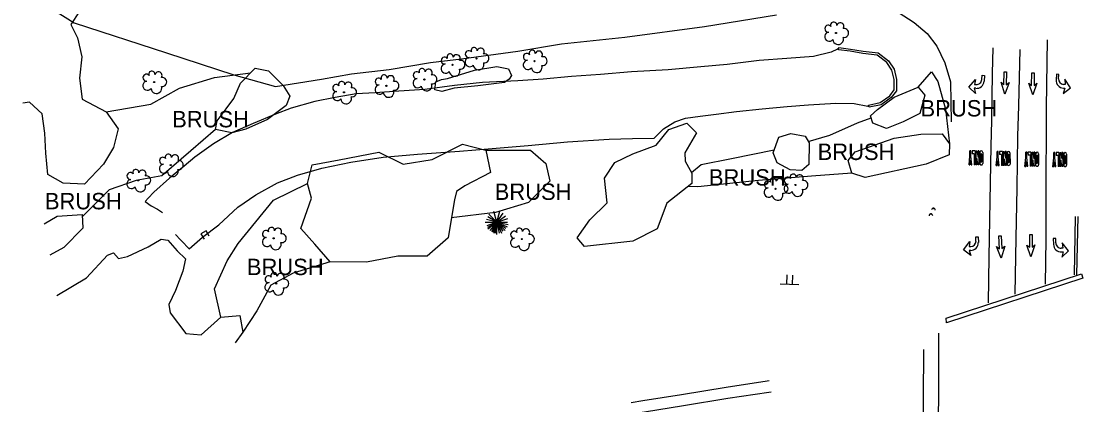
# Model space of a CAD drawing. Extents: x 2129547 to 2134906, y 657330 to 659734.
# Drawn here: x 2132031.2 to 2132484.8, y 657638.7 to 657802.6 of the extents above; entities that cross this region are included whole.
import ezdxf

# ---------------------------------------------------------------- set-up
doc = ezdxf.new("R2010")
doc.units = 0
for name, color, linetype in [('Default', 7, 'Continuous'), ('DR_X_Culvert', 7, 'Continuous'), ('DR_X_Drainage_Area', 7, 'Continuous'), ('PM_X_Arrows', 7, 'Continuous'), ('PM_X_Cells', 7, 'Continuous'), ('PM_X_Channelizing_Line', 7, 'Continuous'), ('PM_X_CL_Double_Solid', 7, 'Continuous'), ('PM_X_Crosswalk', 7, 'Continuous'), ('PM_X_Lane_Line', 7, 'Continuous'), ('PM_X_Stop_Line', 7, 'Continuous'), ('PV_X_Walk', 7, 'Continuous'), ('RD_X_Fence', 7, 'Continuous'), ('SN_X_Public', 7, 'Continuous'), ('UT_X_Misc_Cells', 7, 'Continuous'), ('VG_X_Cells', 7, 'Continuous'), ('VG_X_Shrub_Line_Lt', 7, 'Continuous'), ('VG_X_Text', 7, 'Continuous'), ('VG_X_Tree_Line_Lt', 7, 'Continuous')]:
    doc.layers.add(name, color=color, linetype=linetype)

# ---------------------------------------------------------------- blocks, each defined once
blk = doc.blocks.new('PIPE')
at = {"layer": 'Default'}
for p, q in [((0.135, 0.067), (0, 0.067)), ((0, 0.067), (0, -0.067)), ((0, -0.067), (0.135, -0.067))]:
    blk.add_line(p, q, dxfattribs=at)
blk = doc.blocks.new('DM')
at = {"layer": 'UT_X_Misc_Cells'}
blk.add_circle((0, 0), 0.00254, dxfattribs=at)
blk.add_arc((0.01016, 0), 0.01016, 90, 270, dxfattribs=at)
blk = doc.blocks.new('POINT_DISPLAY')
at = {"layer": 'Default'}
blk.add_line((0, 0), (0, 0), dxfattribs=at)
blk = doc.blocks.new('SGN2P')
at = {"layer": 'Default'}
for p, q in [((0, 0.0061), (-0.0203, 0.0061)), ((0, 0.0203), (0, -0.0203)), ((0, -0.0061), (-0.0203, -0.0061))]:
    blk.add_line(p, q, dxfattribs=at)
blk.add_blockref('POINT_DISPLAY', (0, 0), dxfattribs=at)
blk = doc.blocks.new('TREE')
at = {"layer": 'VG_X_Cells'}
blk.add_circle((0, 0), 0.00305, dxfattribs=at)
for centre, radius, start, end in [((-0.0125, 0.0428), 0.0167, 354.0047, 205.97412), ((-0.0362, -0.0197), 0.0251, 96.17219, 320.57371), ((-0.042, 0.0237), 0.0187, 39.06254, 279.54124), ((0.0232, 0.0359), 0.0197, 323.82996, 165.0376), ((0.0439, 0.0005), 0.0243, 259.14531, 101.45961), ((0.012, -0.0331), 0.029, 184.94757, 19.45715)]:
    blk.add_arc(centre, radius, start, end, dxfattribs=at)
blk = doc.blocks.new('ETREE')
at = {"layer": 'VG_X_Cells'}
for p, q in [((0, 0), (-0.0157, 0.0586)), ((0, 0), (0.016, 0.0597)), ((-0.0627, 0), (0, 0)), ((0, 0), (-0.056, 0.015)), ((0, 0), (-0.0545, -0.0198)), ((0, 0), (-0.0506, -0.029)), ((0, 0), (-0.0496, 0.0292)), ((0, 0), (-0.0496, -0.038)), ((0, 0), (-0.0443, 0.0443)), ((0, 0), (-0.0374, -0.044)), ((0, 0), (-0.0294, -0.051)), ((0, 0), (-0.0211, -0.0551)), ((0, 0), (-0.016, -0.0617)), ((0, 0), (-0.0069, -0.0583)), ((0, 0), (0.0337, 0.0493)), ((0, 0), (0.0464, 0.0356)), ((0, 0), (0.0602, 0.0204)), ((0, 0), (0.0573, 0.0012)), ((0, -0.0665), (0, 0)), ((0, 0), (0.0117, -0.0589)), ((0, 0), (0.0246, -0.0593)), ((0, 0), (0.0322, -0.0482)), ((0, 0), (0.0456, -0.0447)), ((0, 0), (0.0485, -0.0324)), ((0, 0), (0.0567, -0.0247)), ((0, 0), (0.0613, -0.0122))]:
    blk.add_line(p, q, dxfattribs=at)
blk = doc.blocks.new('PMLFT')
at = {"layer": 'PM_X_Cells'}
for points in [[(-0.57, 0), (-0.57, 0), (-0.57, 0.17), (0, 0), (-0.65, 0.76), (-1.54, 0.08), (-0.98, 0.17), (-0.98, -0.01)], [(-1.56, -0.59), (-2.03, -0.59), (-2.03, -0.85), (-1.4, -0.85)]]:
    blk.add_lwpolyline(points, dxfattribs=at)
for centre, radius, end in [((-1.56, -0.01), 0.583, 0), ((-1.4, -0.01), 0.833, 0.9085)]:
    blk.add_arc(centre, radius, 270, end, dxfattribs=at)
blk = doc.blocks.new('PMRT')
at = {"layer": 'PM_X_Cells'}
for points in [[(-1.56, 0.59), (-2.03, 0.59), (-2.03, 0.85), (-1.4, 0.85)], [(-0.57, 0), (-0.57, 0), (-0.57, -0.17), (0, 0), (-0.65, -0.76), (-1.54, -0.08), (-0.98, -0.17), (-0.98, 0.01)]]:
    blk.add_lwpolyline(points, dxfattribs=at)
for centre, radius, start in [((-1.56, 0.01), 0.583, 360), ((-1.4, 0.01), 0.833, 359.0915)]:
    blk.add_arc(centre, radius, start, 90, dxfattribs=at)
blk = doc.blocks.new('PMTHR')
at = {"layer": 'PM_X_Cells'}
blk.add_lwpolyline([(0, 0), (-1.27, -0.44), (-1.02, -0.13), (-2.41, -0.13), (-2.41, 0.13), (-1.02, 0.13), (-1.27, 0.44)], close=True, dxfattribs=at)
blk = doc.blocks.new('PMON8')
at = {"layer": 'Default'}
for p, q in [((-2.03, 0.44), (0, 0.44)), ((-2.03, 0.44), (-2.03, 0.32)), ((-2.03, 0.32), (-1.08, 0.32)), ((-2.03, 0.15), (-1.08, 0.32)), ((-2.03, 0.02), (-2.03, 0.15)), ((-2.03, 0.02), (0, 0.02)), ((-1.82, 0.99), (-0.21, 0.99)), ((-1.82, 0.57), (-0.21, 0.57)), ((-1.52, 0.87), (-0.51, 0.87)), ((-1.52, 0.7), (-0.51, 0.7)), ((0, 0.32), (-0.95, 0.15)), ((-0.95, 0.15), (0, 0.15)), ((0, 0.44), (0, 0.32)), ((0, 0.15), (0, 0.02)), ((-2.03, -0.11), (0, -0.11)), ((-2.03, -0.11), (-2.03, -0.53)), ((-2.03, -0.53), (-1.61, -0.53)), ((-1.27, -0.72), (-2.03, -0.72)), ((-2.03, -0.72), (-2.03, -0.85)), ((-1.27, -0.85), (-2.03, -0.85)), ((-1.61, -0.23), (-1.61, -0.53)), ((-1.61, -0.23), (0, -0.23)), ((0, -0.57), (-1.27, -0.72)), ((0, -0.99), (-1.27, -0.85)), ((0, -0.7), (-0.68, -0.78)), ((0, -0.87), (-0.68, -0.78)), ((0, -0.11), (0, -0.23)), ((0, -0.7), (0, -0.57)), ((0, -0.99), (0, -0.87))]:
    blk.add_line(p, q, dxfattribs=at)
for centre, radius, start, end in [((-1.82, 0.78), 0.212, 90, 270), ((-1.52, 0.78), 0.0847, 90, 270), ((-0.51, 0.78), 0.0847, 270, 90), ((-0.21, 0.78), 0.212, 270, 90)]:
    blk.add_arc(centre, radius, start, end, dxfattribs=at)
for p in [(-2.03, 0), (0, 0)]:
    blk.add_blockref('POINT_DISPLAY', p, dxfattribs=at)

msp = doc.modelspace()

# ---------------------------------------------------------------- linework, layer by layer
at = {"layer": 'DR_X_Culvert'}
msp.add_lwpolyline([(2132380.18, 657791.34), (2132385.27, 657790.69), (2132390.58, 657789.74), (2132397.07, 657789.05), (2132401.44, 657785.59), (2132403.82, 657782.03), (2132404.8, 657777.72), (2132404.86, 657772.86), (2132402.65, 657769.92), (2132398.29, 657766.85), (2132393.17, 657765.77), (2132392.96, 657766.75), (2132397.88, 657767.78), (2132401.94, 657770.65), (2132403.85, 657773.19), (2132403.8, 657777.6), (2132402.88, 657781.63), (2132400.69, 657784.9), (2132396.67, 657788.08), (2132390.43, 657788.75), (2132385.12, 657789.7), (2132380.05, 657790.34)], close=True, dxfattribs=at)
at = {"layer": 'DR_X_Drainage_Area'}
for points in [[(2132380.12, 657790.85), (2132379.71, 657790.64), (2132377.02, 657789.28), (2132369.47, 657787.52), (2132357.97, 657786.7), (2132346.22, 657785.71), (2132332.63, 657784), (2132321.33, 657783.02), (2132307.38, 657781.84), (2132291.69, 657780.87), (2132278.52, 657779.74), (2132266.09, 657778.87), (2132253.98, 657777.82), (2132243.17, 657777.07), (2132228.15, 657776.36), (2132216.1, 657775.1), (2132203.53, 657773.42), (2132192.43, 657772.68), (2132182.36, 657771.93), (2132174.14, 657771.53), (2132165.29, 657770.01), (2132156.52, 657768.21), (2132146.39, 657765.42), (2132139.8, 657762.88), (2132130.18, 657758.81), (2132121.36, 657754.96), (2132113.34, 657750.12), (2132105.36, 657744.47), (2132100.77, 657740.61), (2132094.51, 657735.45), (2132087.79, 657729.46), (2132085.4, 657726.95), (2132084.15, 657725.58), (2132086.69, 657723.69), (2132089.32, 657722.32), (2132091.49, 657720.85)], [(2132097.12, 657711.43), (2132099.19, 657709.17), (2132099.59, 657708.74), (2132102.91, 657705.35), (2132108.55, 657710.29), (2132115.54, 657715.63), (2132123.69, 657723.11), (2132131.42, 657728.43), (2132140.57, 657733.54), (2132149.16, 657736.74), (2132159.6, 657739.81), (2132171.88, 657742.33), (2132185.78, 657744.54), (2132200.38, 657745.79), (2132218.29, 657747.08), (2132232.31, 657748.22), (2132247.61, 657749.52), (2132264.45, 657750.98), (2132282.18, 657752.1), (2132292.14, 657752.43), (2132301.43, 657752.64), (2132305.35, 657756.55), (2132310.29, 657759.52), (2132314.83, 657761.14), (2132321.06, 657761.94), (2132327.88, 657762.81), (2132336.49, 657763.93), (2132347.51, 657765.07), (2132358.23, 657766.08), (2132367.29, 657766.77), (2132378.99, 657767.55), (2132386.84, 657767.34), (2132392.62, 657766.33), (2132393.07, 657766.25)]]:
    msp.add_lwpolyline(points, dxfattribs=at)
at = {"layer": 'PM_X_Channelizing_Line'}
for points in [[(2132468.44, 657690.19), (2132468.69, 657709.47), (2132468.69, 657733.18), (2132468.85, 657757.97), (2132468.93, 657765.72), (2132469.31, 657794.62)], [(2132445.93, 657791.25), (2132445.7, 657780.27), (2132445.35, 657760.17), (2132445.12, 657749.22), (2132444.69, 657725.73), (2132444.3, 657701.93), (2132444.04, 657682.21)]]:
    msp.add_lwpolyline(points, dxfattribs=at)
at = {"layer": 'PM_X_CL_Double_Solid'}
for p, q in [((2132480.86, 657694.16), (2132481.34, 657719.16)), ((2132481.86, 657694.14), (2132482.34, 657719.14))]:
    msp.add_line(p, q, dxfattribs=at)
at = {"layer": 'PM_X_Crosswalk'}
for points in [[(2132534.65, 657677.35), (2132530.77, 657661.09), (2132525.71, 657640.72), (2132521.24, 657623.89), (2132516.54, 657605.77), (2132512.45, 657589.14), (2132495.31, 657586.38), (2132478.53, 657583.9), (2132458.76, 657580.95), (2132439.37, 657577.96), (2132422.84, 657575.72), (2132422.84, 657591.79), (2132422.63, 657608.08), (2132422.81, 657625.36), (2132422.95, 657650.57), (2132422.99, 657669.31)], [(2132416.36, 657662.33), (2132416.31, 657641.39), (2132416.34, 657624.06), (2132416.32, 657608.43), (2132416.1, 657589.48), (2132416.03, 657573.91)]]:
    msp.add_lwpolyline(points, dxfattribs=at)
at = {"layer": 'PM_X_Lane_Line'}
msp.add_lwpolyline([(2132457.54, 657790.46), (2132456.92, 657766.41), (2132456.46, 657753.4), (2132456.28, 657731.21), (2132455.86, 657709.97), (2132455.41, 657685.95)], dxfattribs=at)
at = {"layer": 'PM_X_Stop_Line'}
msp.add_lwpolyline([(2132484.42, 657692.74), (2132426.26, 657673.7), (2132426, 657675.73), (2132483.79, 657694.67)], close=True, dxfattribs=at)
at = {"layer": 'PV_X_Walk'}
for points in [[(2132350.47, 657648.87), (2132349.63, 657648.74), (2132332.16, 657646.04), (2132313.12, 657642.92), (2132296.58, 657640.33), (2132291.56, 657639.54)], [(2132351.29, 657644.14), (2132350.37, 657644), (2132332.92, 657641.3), (2132313.88, 657638.18), (2132297.33, 657635.58), (2132292.42, 657634.81)]]:
    msp.add_lwpolyline(points, dxfattribs=at)
at = {"layer": 'RD_X_Fence'}
for points in [[(2132031.21, 657816.21), (2132053.76, 657801.86), (2132093.2, 657789.04), (2132121.96, 657779.72), (2132139.74, 657774.63), (2132159.35, 657777.78), (2132172.17, 657780.04), (2132188.33, 657781.96), (2132205.93, 657784.87), (2132219.21, 657786.45), (2132243.16, 657789.79), (2132261.84, 657792.9), (2132288.84, 657795.78), (2132322.87, 657800.28), (2132353.63, 657805.31)], [(2132405.58, 657806.42), (2132412.34, 657802.05), (2132417.89, 657797.32), (2132422.01, 657791.93), (2132425.42, 657784.82), (2132427.92, 657776.62), (2132428.17, 657759.63)]]:
    msp.add_lwpolyline(points, dxfattribs=at)
at = {"layer": 'VG_X_Shrub_Line_Lt'}
for points in [[(2132067.4, 657763.86), (2132086.53, 657767.12), (2132098.81, 657773.91), (2132113.7, 657778.52), (2132129.09, 657780.5)], [(2132414.07, 657774.36), (2132419.82, 657780.98), (2132422.46, 657776.82), (2132425.75, 657764.93), (2132427.52, 657750.2)], [(2132367.18, 657751.19), (2132376.38, 657753.94), (2132388.17, 657759.11), (2132393.99, 657761.34)], [(2132114.18, 657756.32), (2132103.64, 657747.13), (2132091.16, 657736.43), (2132080.27, 657734.55), (2132068.73, 657730.56), (2132057.25, 657719.05)], [(2132229.61, 657747.46), (2132248.67, 657747.43), (2132255.1, 657741.81), (2132256.8, 657734.28), (2132247.76, 657725.04), (2132233.65, 657720.86), (2132214.81, 657718.54)], [(2132317.32, 657737.98), (2132321.45, 657741.41), (2132334.37, 657743.96), (2132352.69, 657747.61)], [(2132385.74, 657737.61), (2132368.59, 657736.33), (2132345.9, 657734.51), (2132320.01, 657731.86), (2132315.84, 657731.96)], [(2132116.4, 657676.13), (2132113.67, 657688.18), (2132119.15, 657700.19), (2132123.77, 657707.53), (2132138.95, 657726.05), (2132153.43, 657733.29)], [(2132163.13, 657699.81), (2132147.24, 657694.91), (2132137.7, 657689.84), (2132131.82, 657678.8), (2132125.83, 657669.64)]]:
    msp.add_lwpolyline(points, dxfattribs=at)
at = {"layer": 'VG_X_Tree_Line_Lt'}
for points in [[(2132056, 657806.61), (2132052.44, 657801.19), (2132055.16, 657795.46), (2132057.13, 657787.3), (2132056.07, 657778.23), (2132057.18, 657769.26), (2132067.4, 657763.86), (2132072.65, 657756.58), (2132070.58, 657748.65), (2132066.39, 657741.45), (2132058.26, 657732.91), (2132049.04, 657733.34), (2132042.49, 657737.12), (2132041.64, 657746.25), (2132041.26, 657754.75), (2132040.17, 657762.95), (2132034.69, 657767.95), (2132031.9, 657767.58)], [(2132041.02, 657716), (2132046.53, 657719.23), (2132057.19, 657720.02), (2132057.57, 657714.09), (2132049.35, 657705.91), (2132043.39, 657702.61)], [(2132046.45, 657685.33), (2132059.1, 657692.85), (2132068.06, 657702.62), (2132070.65, 657703.56), (2132072.76, 657701.14), (2132076.51, 657702.05), (2132085.44, 657706.19), (2132090.88, 657709.46), (2132093.8, 657708.96), (2132097.75, 657704.41), (2132101.32, 657701.07), (2132100.24, 657695.78), (2132097.04, 657687.49), (2132094.23, 657681.54), (2132094.82, 657677.92), (2132101.48, 657669.2), (2132108.01, 657668.51), (2132116.4, 657676.13), (2132124.47, 657676.84), (2132125.83, 657669.64), (2132122.54, 657665.21)]]:
    msp.add_lwpolyline(points, dxfattribs=at)
for points in [[(2132121.9, 657769.55), (2132124.83, 657776.12), (2132131.11, 657782.57), (2132136.83, 657781.43), (2132143.03, 657775.15), (2132145.93, 657770.55), (2132144.33, 657766.6), (2132136.32, 657760.5), (2132127.03, 657756.47), (2132121.15, 657754.91), (2132114.18, 657756.32), (2132114.82, 657760.05), (2132118.71, 657765.12)], [(2132213.22, 657778.13), (2132224.69, 657781.64), (2132234.25, 657783.23), (2132239.23, 657782.25), (2132240.52, 657779.41), (2132239.46, 657777.78), (2132237.49, 657776.44), (2132226.1, 657774.94), (2132216.09, 657774.01), (2132210.71, 657772.57), (2132207.79, 657773.25), (2132208.19, 657776.6), (2132210.6, 657777.68)], [(2132396.77, 657764.9), (2132403.82, 657770.08), (2132414.07, 657774.36), (2132416.98, 657770.91), (2132414.8, 657763.1), (2132407.68, 657759.53), (2132400.59, 657756.75), (2132394.81, 657758.95), (2132393.73, 657762.07)], [(2132317.46, 657733.24), (2132306.76, 657724.81), (2132302.73, 657713.92), (2132292.29, 657708.55), (2132271.68, 657706.35), (2132268.6, 657710), (2132274, 657717.68), (2132281.28, 657724.97), (2132280.17, 657735.53), (2132284.58, 657742.21), (2132292.36, 657745.89), (2132302.23, 657749.67), (2132307.69, 657756.29), (2132315.41, 657758.95), (2132319.48, 657754.83), (2132314.5, 657746.29), (2132314.62, 657742.74), (2132317.53, 657737.6)], [(2132352.26, 657746.38), (2132354.56, 657752.96), (2132359.74, 657754.57), (2132365.93, 657753.5), (2132367.53, 657750.54), (2132367.44, 657741.3), (2132364.4, 657738.82), (2132359.53, 657739.11), (2132353.92, 657742.06)], [(2132387.21, 657746.7), (2132403.93, 657752.64), (2132415.29, 657754.31), (2132424.34, 657754.4), (2132427.52, 657750.2), (2132427.31, 657745.53), (2132417.58, 657741.44), (2132391.47, 657735.72), (2132385.74, 657737.61), (2132384.18, 657743.03)], [(2132216.12, 657726.23), (2132214.25, 657715.26), (2132213.48, 657710.08), (2132204.53, 657702.13), (2132192.01, 657702.21), (2132178.58, 657699.68), (2132163.13, 657699.81), (2132156.49, 657707.28), (2132150.57, 657713.94), (2132155.05, 657727), (2132153.43, 657733.29), (2132155.38, 657741.21), (2132166.96, 657743.37), (2132183.8, 657746.65), (2132194.26, 657741.46), (2132206.63, 657743.51), (2132219.63, 657750.01), (2132229.61, 657747.46), (2132231.56, 657737.99), (2132220.55, 657732.25), (2132217.08, 657729.76)]]:
    msp.add_lwpolyline(points, close=True, dxfattribs=at)

# ---------------------------------------------------------------- block references
at = {"layer": 'DR_X_Culvert', "xscale": 19.684999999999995, "yscale": 19.68499999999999, "rotation": -58.42957639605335}
msp.add_blockref('PIPE', (2132108.98, 657712.35), dxfattribs=at)
at = {"layer": 'PM_X_Arrows'}
for name, p, xscale, yscale, rotation in [('PMRT', (2132438.53, 657771.65), 3.9370000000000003, 3.9370000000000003, -93.94159714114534), ('PMTHR', (2132451.07, 657771.41), 3.9370000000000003, 3.9370000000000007, -91.80284121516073), ('PMTHR', (2132463.02, 657771.08), 3.9370000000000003, 3.9370000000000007, -90.6838800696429), ('PMLFT', (2132475.94, 657771.71), 3.9370000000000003, 3.9370000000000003, -94.14751045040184), ('PMON8', (2132438.76, 657741.15), 2.952749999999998, 2.9527499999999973, -89.73717717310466), ('PMON8', (2132450.39, 657740.91), 2.9527499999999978, 2.952749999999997, -89.73717717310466), ('PMON8', (2132462.58, 657740.57), 2.9527499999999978, 2.952749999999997, -89.73717717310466), ('PMON8', (2132474.57, 657740.43), 2.9527499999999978, 2.952749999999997, -89.73717717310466), ('PMRT', (2132436.55, 657702.42), 3.937, 3.9370000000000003, -89.17424292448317), ('PMTHR', (2132449.6, 657701.38), 3.937, 3.9370000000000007, -86.76192348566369), ('PMTHR', (2132462.26, 657701.95), 3.9369999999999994, 3.9370000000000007, -89.8524258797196), ('PMLFT', (2132475.38, 657701.77), 3.9370000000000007, 3.9370000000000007, -88.2325008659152)]:
    msp.add_blockref(name, p, dxfattribs=dict(at, xscale=xscale, yscale=yscale, rotation=rotation))
at = {"layer": 'SN_X_Public', "xscale": 196.85000000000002, "yscale": 196.85, "rotation": -92.45877252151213}
msp.add_blockref('SGN2P', (2132359.22, 657690.09), dxfattribs=at)
at = {"layer": 'UT_X_Misc_Cells'}
for p, xscale, yscale, rotation in [((2132419.57, 657720.2), 78.74000000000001, 78.74000000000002, -91.80513332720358), ((2132420.66, 657722.67), 78.74000000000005, 78.74000000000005, -93.56607428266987)]:
    msp.add_blockref('DM', p, dxfattribs=dict(at, xscale=xscale, yscale=yscale, rotation=rotation))
at = {"layer": 'VG_X_Cells', "xscale": 78.74000000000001, "yscale": 78.74000000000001}
for name, p in [('TREE', (2132379.03, 657797.52)), ('TREE', (2132215.27, 657783.9)), ('TREE', (2132225.52, 657786.64)), ('TREE', (2132250.34, 657785.47)), ('TREE', (2132087.95, 657776.57)), ('TREE', (2132187.09, 657774.93)), ('TREE', (2132203.31, 657777.66)), ('TREE', (2132168.98, 657772.17)), ('TREE', (2132095, 657741.09)), ('TREE', (2132081.1, 657734.56)), ('TREE', (2132361.7, 657732.59)), ('TREE', (2132353.17, 657730.93)), ('ETREE', (2132234.25, 657716.66)), ('TREE', (2132138.96, 657709.81)), ('TREE', (2132244.89, 657709.48)), ('TREE', (2132140.05, 657690.45))]:
    msp.add_blockref(name, p, dxfattribs=at)

# ---------------------------------------------------------------- texts
at = {"layer": 'VG_X_Text'}
for p in [(2132415.11, 657761.87), (2132095.64, 657757.21), (2132371.2, 657743.27), (2132324.78, 657732.33), (2132233.34, 657726.22), (2132041.32, 657722.19), (2132127.54, 657694.09)]:
    msp.add_text('BRUSH', height=7, dxfattribs=at).set_placement(p)

doc.saveas('drawing.dxf')
